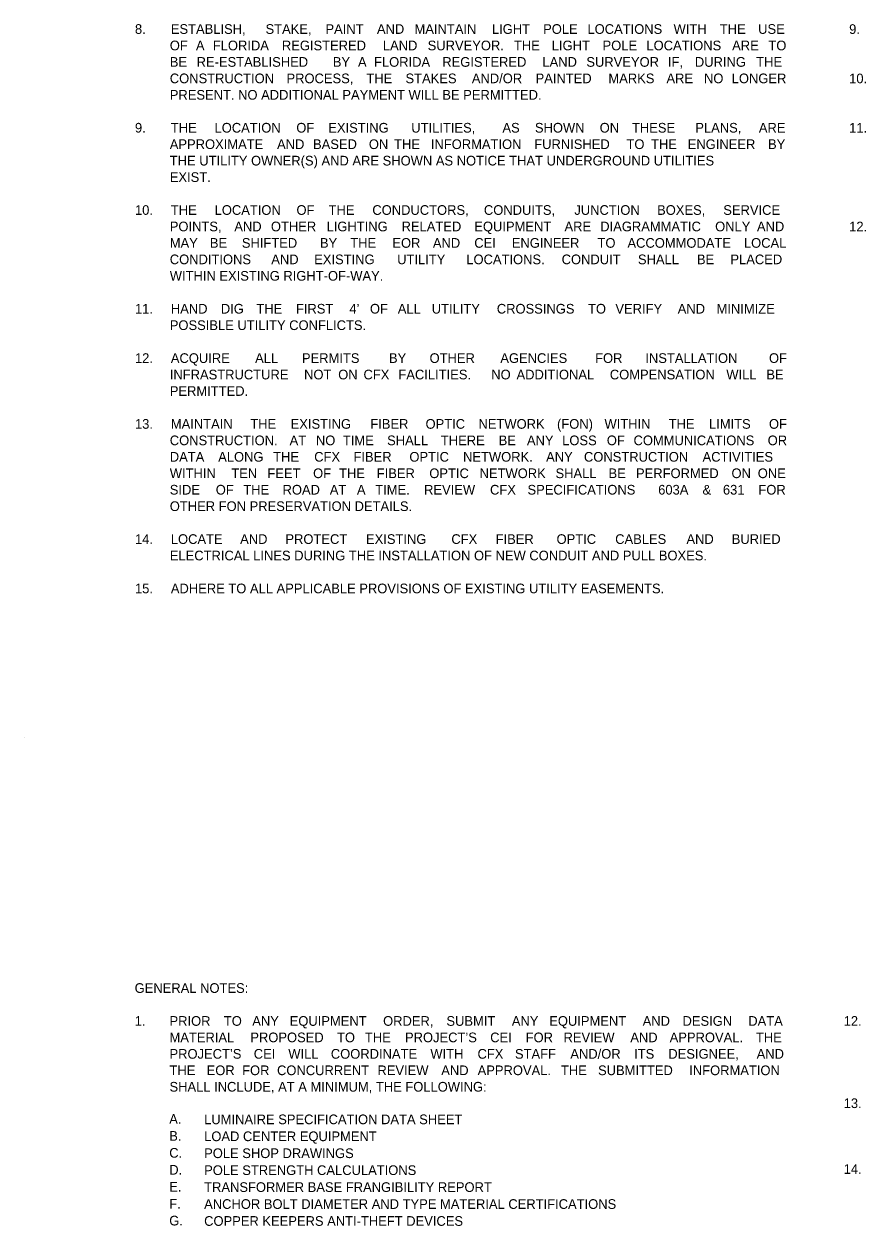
# Model space of a CAD drawing. Extents: x -55 to 2471539, y -90 to 3608906.
# Drawn here: x -54 to 555, y 780 to 1649 of the extents above; entities that cross this region are included whole.
import ezdxf

# ---------------------------------------------------------------- set-up
doc = ezdxf.new("R2010")
doc.units = 0
doc.layers.add('TextMinor', color=7, linetype='Continuous')
doc.layers.add('XSCell', color=7, linetype='Continuous')

msp = doc.modelspace()

# ---------------------------------------------------------------- linework, layer by layer
at = {"layer": 'TextMinor'}
msp.add_line((-54.3, 1133.16), (-54.3, 1133.16), dxfattribs=at)

# ---------------------------------------------------------------- texts
at = {"layer": 'XSCell'}
for s, p in [('8.', (25.93, 1642.28)), ('ESTABLISH, ', (51.88, 1642.28)), ('STAKE, ', (120.37, 1642.28)), ('PAINT ', (163.7, 1642.28)), ('AND ', (200.95, 1642.28)), ('MAINTAIN ', (228.11, 1642.28)), ('LIGHT ', (284.09, 1642.28)), ('POLE ', (321.15, 1642.28)), ('LOCATIONS ', (353.19, 1642.28)), ('WITH ', (415.49, 1642.28)), ('THE ', (448.94, 1642.28)), ('USE ', (476.64, 1642.28)), ('9.', (542.46, 1642.24)), ('OF ', (51.12, 1630.38)), ('A ', (70.02, 1630.38)), ('FLORIDA ', (82.24, 1630.38)), ('REGISTERED ', (132.19, 1630.38)), ('LAND ', (205.23, 1630.38)), ('SURVEYOR. ', (237.62, 1630.38)), ('THE ', (299.99, 1630.38)), ('LIGHT ', (327.38, 1630.38)), ('POLE ', (364.11, 1630.38)), ('LOCATIONS ', (395.84, 1630.38)), ('ARE ', (457.83, 1630.38)), ('TO ', (484.06, 1630.38)), ('RE-ESTABLISHED ', (70.53, 1618.48)), ('FLORIDA ', (198.84, 1618.48)), ('REGISTERED ', (248.18, 1618.48)), ('SURVEYOR ', (352.39, 1618.48)), ('DURING ', (430.89, 1618.48)), ('BE ', (51.12, 1618.48)), ('BY ', (169.03, 1618.48)), ('A ', (187.23, 1618.48)), ('LAND ', (320.61, 1618.48)), ('IF, ', (411.39, 1618.48)), ('THE ', (475.23, 1618.48)), ('CONSTRUCTION ', (51.12, 1606.58)), ('PROCESS, ', (135.53, 1606.58)), ('THE ', (193.29, 1606.58)), ('STAKES ', (221.6, 1606.58)), ('AND/OR ', (269.57, 1606.58)), ('PAINTED ', (315.68, 1606.58)), ('MARKS ', (368.35, 1606.58)), ('ARE ', (410.33, 1606.58)), ('NO ', (437.49, 1606.58)), ('LONGER ', (457.53, 1606.58)), ('10.', (542.46, 1606.54)), ('PRESENT. NO ADDITIONAL PAYMENT WILL BE PERMITTED.', (51.12, 1594.68)), ('9.', (25.93, 1570.88)), ('THE ', (51.88, 1570.88)), ('LOCATION ', (83.48, 1570.88)), ('OF ', (142.62, 1570.88)), ('EXISTING ', (165.74, 1570.88)), ('UTILITIES, ', (225.78, 1570.88)), ('AS ', (291.68, 1570.88)), ('SHOWN ', (315.2, 1570.88)), ('ON ', (362.04, 1570.88)), ('THESE ', (385.38, 1570.88)), ('PLANS, ', (431.2, 1570.88)), ('ARE ', (477.14, 1570.88)), ('11.', (542.46, 1570.84)), ('APPROXIMATE ', (51.12, 1558.98)), ('AND ', (128.7, 1558.98)), ('BASED ', (154.72, 1558.98)), ('ON ', (195.09, 1558.98)), ('THE ', (213.38, 1558.98)), ('INFORMATION ', (239.94, 1558.98)), ('FURNISHED ', (314.71, 1558.98)), ('TO ', (381.43, 1558.98)), ('THE ', (399.16, 1558.98)), ('ENGINEER ', (425.72, 1558.98)), ('BY ', (483.8, 1558.98)), ('THE UTILITY OWNER(S) AND ARE SHOWN AS NOTICE THAT UNDERGROUND UTILITIES ', (51.12, 1547.08)), ('EXIST.', (51.12, 1535.18)), ('10.', (25.93, 1511.38)), ('THE ', (51.88, 1511.38)), ('LOCATION ', (83.55, 1511.38)), ('OF ', (142.75, 1511.38)), ('THE ', (165.94, 1511.38)), ('CONDUCTORS, ', (197.62, 1511.38)), ('CONDUITS, ', (278.3, 1511.38)), ('JUNCTION ', (343.7, 1511.38)), ('BOXES, ', (403.57, 1511.38)), ('SERVICE ', (451.42, 1511.38)), ('POINTS, ', (51.12, 1499.48)), ('AND ', (97.78, 1499.48)), ('OTHER ', (124.25, 1499.48)), ('LIGHTING ', (164.51, 1499.48)), ('RELATED ', (218.76, 1499.48)), ('EQUIPMENT ', (271.36, 1499.48)), ('ARE ', (336.58, 1499.48)), ('DIAGRAMMATIC ', (362.44, 1499.48)), ('ONLY ', (445.54, 1499.48)), ('AND ', (475.77, 1499.48)), ('12.', (542.46, 1499.44)), ('MAY ', (51.12, 1487.58)), ('BE ', (80.1, 1487.58)), ('SHIFTED ', (103.22, 1487.58)), ('BY ', (159.71, 1487.58)), ('THE ', (181.63, 1487.58)), ('EOR ', (212.11, 1487.58)), ('AND ', (241.4, 1487.58)), ('CEI ', (271.34, 1487.58)), ('ENGINEER ', (298.47, 1487.58)), ('TO ', (360.47, 1487.58)), ('ACCOMMODATE ', (382.12, 1487.58)), ('LOCAL ', (466.36, 1487.58)), ('CONDITIONS ', (51.12, 1475.68)), ('AND ', (124.51, 1475.68)), ('EXISTING ', (155.55, 1475.68)), ('UTILITY ', (215.58, 1475.68)), ('LOCATIONS. ', (265.58, 1475.68)), ('CONDUIT ', (334.53, 1475.68)), ('SHALL ', (389.71, 1475.68)), ('BE ', (432.37, 1475.68)), ('PLACED ', (456.59, 1475.68)), ('WITHIN EXISTING RIGHT-OF-WAY.', (51.12, 1463.78)), ('11.', (25.93, 1439.98)), ('HAND ', (51.88, 1439.98)), ('DIG ', (88.04, 1439.98)), ('THE ', (113.72, 1439.98)), ('FIRST ', (142.35, 1439.98)), ('4’ ', (180.98, 1439.98)), ('OF ', (195.88, 1439.98)), ('ALL ', (216.02, 1439.98)), ('UTILITY ', (240.58, 1439.98)), ('CROSSINGS ', (287.63, 1439.98)), ('TO ', (353.61, 1439.98)), ('VERIFY ', (373.41, 1439.98)), ('AND ', (418.48, 1439.98)), ('MINIMIZE ', (446.58, 1439.98)), ('POSSIBLE UTILITY CONFLICTS.', (51.12, 1428.08)), ('12.', (25.93, 1404.28)), ('ACQUIRE ', (51.88, 1404.28)), ('ALL ', (112.83, 1404.28)), ('PERMITS ', (146.69, 1404.28)), ('BY ', (209.63, 1404.28)), ('OTHER ', (239, 1404.28)), ('AGENCIES ', (290.18, 1404.28)), ('FOR ', (358.74, 1404.28)), ('INSTALLATION ', (395.06, 1404.28)), ('OF ', (484.48, 1404.28)), ('INFRASTRUCTURE ', (51.12, 1392.38)), ('NOT ', (148.26, 1392.38)), ('ON ', (172.92, 1392.38)), ('CFX ', (191.2, 1392.38)), ('FACILITIES. ', (216.47, 1392.38)), ('NO ', (283.62, 1392.38)), ('ADDITIONAL ', (301.9, 1392.38)), ('COMPENSATION ', (369.37, 1392.38)), ('WILL ', (453.64, 1392.38)), ('BE ', (482.6, 1392.38)), ('PERMITTED.', (51.12, 1380.48)), ('13.', (25.93, 1356.68)), ('MAINTAIN ', (51.88, 1356.68)), ('THE ', (109.34, 1356.68)), ('EXISTING ', (138.52, 1356.68)), ('FIBER ', (196.14, 1356.68)), ('OPTIC ', (236.08, 1356.68)), ('NETWORK ', (274.38, 1356.68)), ('(FON) ', (331.18, 1356.68)), ('WITHIN ', (365.51, 1356.68)), ('THE ', (411.91, 1356.68)), ('LIMITS ', (441.09, 1356.68)), ('OF ', (484.48, 1356.68)), ('CONSTRUCTION. ', (51.12, 1344.78)), ('AT ', (137.78, 1344.78)), ('NO ', (156.79, 1344.78)), ('TIME ', (176.31, 1344.78)), ('SHALL ', (208.3, 1344.78)), ('THERE ', (247.17, 1344.78)), ('BE ', (288.98, 1344.78)), ('ANY ', (309.41, 1344.78)), ('LOSS ', (334.92, 1344.78)), ('OF ', (367.21, 1344.78)), ('COMMUNICATIONS ', (386.52, 1344.78)), ('OR ', (483.56, 1344.78)), ('DATA ', (51.12, 1332.88)), ('ALONG ', (86.11, 1332.88)), ('THE ', (125.89, 1332.88)), ('CFX ', (155.57, 1332.88)), ('FIBER ', (183.98, 1332.88)), ('OPTIC ', (224.42, 1332.88)), ('NETWORK. ', (263.22, 1332.88)), ('ANY ', (323.28, 1332.88)), ('CONSTRUCTION ', (350.66, 1332.88)), ('ACTIVITIES ', (436.44, 1332.88)), ('WITHIN ', (51.12, 1320.98)), ('TEN ', (95.6, 1320.98)), ('FEET ', (121.73, 1320.98)), ('OF ', (154.77, 1320.98)), ('THE ', (173.54, 1320.98)), ('FIBER ', (200.8, 1320.98)), ('OPTIC ', (238.82, 1320.98)), ('NETWORK ', (275.2, 1320.98)), ('SHALL ', (330.08, 1320.98)), ('BE ', (368.42, 1320.98)), ('PERFORMED ', (388.31, 1320.98)), ('ON ', (457.38, 1320.98)), ('ONE ', (476.37, 1320.98)), ('SIDE ', (51.12, 1309.08)), ('OF ', (84.37, 1309.08)), ('THE ', (104.28, 1309.08)), ('ROAD ', (132.68, 1309.08)), ('AT ', (166.85, 1309.08)), ('A ', (186.46, 1309.08)), ('TIME. ', (199.69, 1309.08)), ('REVIEW ', (235.03, 1309.08)), ('CFX ', (282.72, 1309.08)), ('SPECIFICATIONS ', (309.84, 1309.08)), ('603A ', (404.34, 1309.08)), ('& ', (436.43, 1309.08)), ('631 ', (451.16, 1309.08)), ('FOR ', (476.84, 1309.08)), ('OTHER FON PRESERVATION DETAILS.', (51.12, 1297.18)), ('14.', (25.93, 1273.38)), ('LOCATE ', (51.88, 1273.38)), ('AND ', (102, 1273.38)), ('PROTECT ', (134.75, 1273.38)), ('EXISTING ', (193.03, 1273.38)), ('CFX ', (254.76, 1273.38)), ('FIBER ', (286.78, 1273.38)), ('OPTIC ', (330.84, 1273.38)), ('CABLES ', (373.25, 1273.38)), ('AND ', (424.79, 1273.38)), ('BURIED ', (457.54, 1273.38)), ('ELECTRICAL LINES DURING THE INSTALLATION OF NEW CONDUIT AND PULL BOXES.', (51.12, 1261.48)), ('15.', (25.93, 1237.68)), ('ADHERE TO ALL APPLICABLE PROVISIONS OF EXISTING UTILITY EASEMENTS.', (51.88, 1237.68)), ('GENERAL NOTES:', (25.72, 948.68)), ('1.', (25.72, 924.88)), ('PRIOR ', (50.92, 924.88)), ('TO ', (90.22, 924.88)), ('ANY ', (110.76, 924.88)), ('EQUIPMENT ', (137.83, 924.88)), ('ORDER, ', (205.4, 924.88)), ('SUBMIT ', (251.19, 924.88)), ('ANY ', (298.48, 924.88)), ('EQUIPMENT ', (325.55, 924.88)), ('AND ', (393.12, 924.88)), ('DESIGN ', (421.95, 924.88)), ('DATA ', (469.51, 924.88)), ('12.', (538.51, 924.88)), ('MATERIAL ', (50.92, 912.98)), ('PROPOSED ', (109.37, 912.98)), ('TO ', (172.05, 912.98)), ('THE ', (192.22, 912.98)), ('PROJECT’S ', (221.23, 912.98)), ('CEI ', (282.84, 912.98)), ('FOR ', (308.49, 912.98)), ('REVIEW ', (335.89, 912.98)), ('AND ', (384.18, 912.98)), ('APPROVAL. ', (412.65, 912.98)), ('THE ', (475.03, 912.98)), ('PROJECT’S ', (50.92, 901.08)), ('CEI ', (111.85, 901.08)), ('WILL ', (136.83, 901.08)), ('COORDINATE ', (167.58, 901.08)), ('WITH ', (239.59, 901.08)), ('CFX ', (273.68, 901.08)), ('STAFF ', (300.75, 901.08)), ('AND/OR ', (340.81, 901.08)), ('ITS ', (386.95, 901.08)), ('DESIGNEE, ', (411.69, 901.08)), ('AND ', (475.56, 901.08)), ('THE ', (50.92, 889.18)), ('EOR ', (77.78, 889.18)), ('FOR ', (103.44, 889.18)), ('CONCURRENT ', (128.68, 889.18)), ('REVIEW ', (201.3, 889.18)), ('AND ', (247.45, 889.18)), ('APPROVAL. ', (273.76, 889.18)), ('THE ', (333.99, 889.18)), ('SUBMITTED ', (360.85, 889.18)), ('INFORMATION ', (426.82, 889.18)), ('SHALL INCLUDE, AT A MINIMUM, THE FOLLOWING:', (50.92, 877.28)), ('13.', (538.51, 865.38)), ('A.', (50.72, 853.98)), ('LUMINAIRE SPECIFICATION DATA SHEET', (75.97, 853.71)), ('B.', (50.72, 841.73)), ('LOAD CENTER EQUIPMENT', (75.97, 841.46)), ('C.', (50.72, 829.48)), ('POLE SHOP DRAWINGS', (75.97, 829.21)), ('D.', (50.72, 817.23)), ('POLE STRENGTH CALCULATIONS', (75.97, 816.96)), ('14.', (538.51, 817.78)), ('E.', (50.72, 804.98)), ('TRANSFORMER BASE FRANGIBILITY REPORT', (75.97, 804.71)), ('F.', (50.72, 792.73)), ('ANCHOR BOLT DIAMETER AND TYPE MATERIAL CERTIFICATIONS', (75.97, 792.46)), ('G.', (50.72, 780.48)), ('COPPER KEEPERS ANTI-THEFT DEVICES', (75.97, 780.21))]:
    msp.add_text(s, height=7, dxfattribs=at).set_placement(p)

doc.saveas('drawing.dxf')
